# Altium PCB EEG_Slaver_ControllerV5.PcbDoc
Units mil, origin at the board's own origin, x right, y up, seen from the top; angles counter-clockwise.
Board outline 393.7 x 394 mil, 4 copper layers (Top Layer, GND, PWR, Bottom Layer), stack 30.634 mil thick; 41 components, 37 nets, 150 pads, 28 vias.
Unrouted connection lines stored in the file: 20.
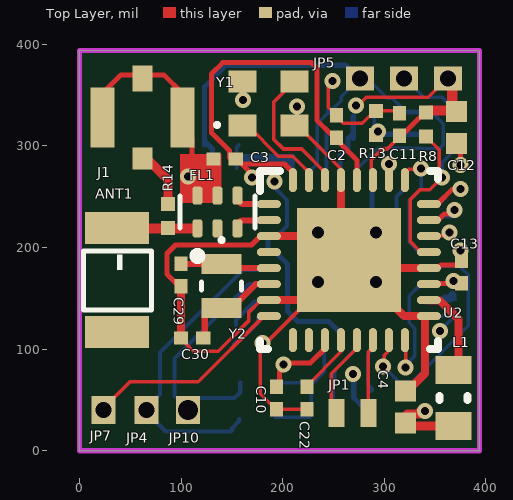
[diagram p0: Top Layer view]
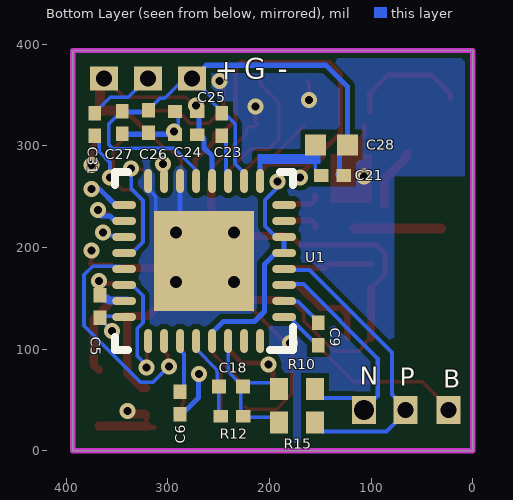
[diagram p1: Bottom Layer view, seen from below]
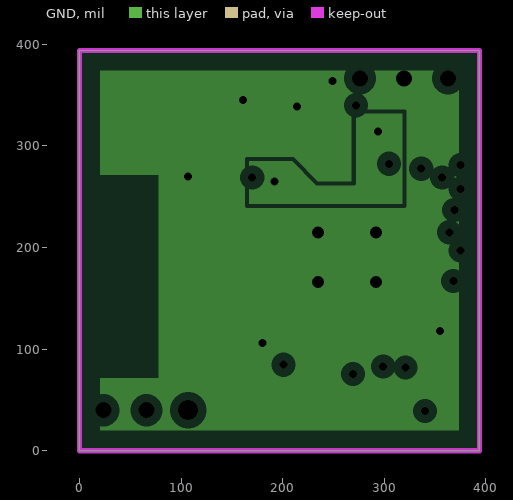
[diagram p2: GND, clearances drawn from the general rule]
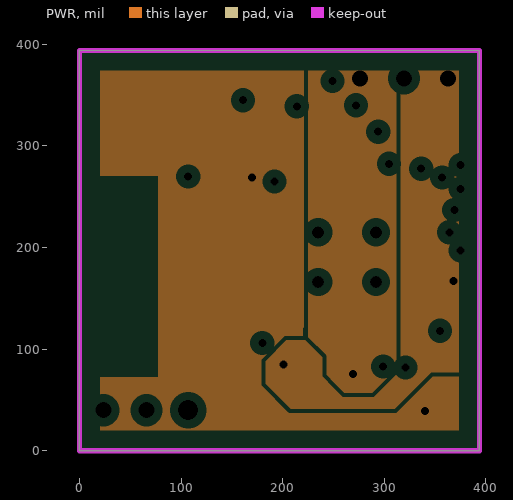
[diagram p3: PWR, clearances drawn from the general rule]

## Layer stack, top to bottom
Top Solder: solder mask 0.4, Solder Resist, Dk 3.5
Top Layer: signal copper 1.4
Dielectric 1: core 10, FR-4, Dk 4.2
GND: plane copper 1.417, net (Multiple Nets)
Dielectric 3: prepreg 5, Dk 4.2
PWR: plane copper 1.417, net (Multiple Nets)
Dielectric 2: core 10, Dk 4.2
Bottom Layer: signal copper 1.4
Bottom Solder: solder mask 0.4, Solder Resist, Dk 3.5

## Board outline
0,0 0,394 393.7,393.7 393.7,0

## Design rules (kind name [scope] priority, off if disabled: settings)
Clearance [All] p1: gap=5 ignorepadtopadclearanceinfootprint=FALSE except(3.5: Arc-Arc Arc-Track Track-Track)
DiffPairsRouting [All] p1: maxlimit=10 minlimit=10 mostfreqgap=10 toplayer_minwidth=3 toplayer_maxwidth=15 toplayer_prefwidth=15 bottomlayer_minwidth=3 bottomlayer_maxwidth=15 bottomlayer_prefwidth=15 maxuncoupledlength=500
MinimumSolderMaskSliver [All] p1: minsoldermaskwidth=8
PlaneClearance [All] p1: clearance=8
PlaneConnect [All] p1: planeconnectstyle=Direct reliefexpansion=20 reliefentries=4 reliefconductorwidth=10 reliefairgap=10
PolygonConnect [All] p1: connectstyle=Direct reliefconductorwidth=10 reliefentries=4 polygonreliefangle="90 Angle" airgapwidth=10
RoutingCorners [All] p1: cornerstyle=45-Degree minsetback=3.94 maxsetback=100
RoutingVias [All] p1: holewidth=7.87 width=15.75 viastyle="Through Hole" minholewidth=5.91 minwidth=11.81 maxholewidth=19.68 maxwidth=31.5
SolderMaskExpansion [All] p1: expansion=4
Width [All] p1: maxlimit=11 minlimit=3.5 preferedwidth=3.5 minimp=50.000000 maximp=50.000000 favimp=50.000000
25 further rules are at their usual default settings.

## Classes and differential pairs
differential pair IN1: +IN1_P -IN1_N
differential pair RF: +RF_P -RF_N

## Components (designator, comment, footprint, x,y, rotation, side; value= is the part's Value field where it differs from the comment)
ANT1 "2450AT18B100E" ANT_2450AT18B100E 37,168 r90 top
C2 "CAP" CAPC0201(0603)33_L 253,319 r90 top value=0.1uF
C3 "CAP" CAPC0201(0603)33_L 143,287 r180 top value=0.1uF
C4 "CAP" CAPC0402(1005)33_L 321,43 r90 top value=10uF
C5 "CAP" CAPC0201(0603)33_L 367,142 r90 bottom value=0.1uF
C6 "CAP" CAPC0201(0603)33_L 288,47 r90 bottom value=1uF
C9 "CAP" CAPC0201(0603)33_L 152,115.02 r90 bottom value=4.7nF
C10 "CAP" CAPC0201(0603)33_L 194,52 r270 top value=0.1uF
C11 "CAP" CAPC0201(0603)33_L 315,321 r90 top value=0.1uF
C12 "CAP" CAPC0402(1005)33_L 371,318 r270 top value=10uF
C13 "CAP" CAPC0201(0603)33_L 376,176 r90 top value=0.1uF
C18 "CAP" CAPC0201(0603)33_L 237,34 r180 bottom value=1.5nF
C21 "CAP" CAPC0201(0603)33_L 138,271 r0 bottom value=0.1uF
C22 "CAP" CAPC0201(0603)33_L 224,52 r270 top value=1uF
C23 "CAP" CAPC0201(0603)33_L 247,321 r270 bottom value=1uF
C24 "CAP" CAPC0201(0603)33_L 282,311 r180 bottom value=1uF
C25 "CAP" CAPC0201(0603)33_L 282,334 r180 bottom value=0.1uF
C26 "CAP" CAPC0201(0603)33_L 319,324 r90 bottom value=1uF
C27 "CAP" CAPC0201(0603)33_L 345,323 r90 bottom value=0.1uF
C28 "CAP" CAPC0402(1005)33_L 139,301 r0 bottom value=10uF
C29 "CAP" CAPC0201(0603)33_L 100,173 r270 top value=12pF
C30 "CAP" CAPC0201(0603)33_L 111,111 r180 top value=12pF
C31 "CAP" CAPC0201(0603)33_L 372,321 r90 bottom value=0.1uF
FL1 "2450BM14G0011T" BALUN_2450BM14G0011T 135.83,235 r90 top
J1 "CONREVSMA001-SMD-G" KH-IPEX3-2020 62,328 r90 top
JP1 "CON2" connect2 253,37 r0 top
JP4 "CON1" CON1_0.4#1 163,21.41 r90 top
JP5 "CON3" con3_0.5 319.49,366.52 r0 top
JP7 "CON1" CON1_0.4#2 53.55,77.41 r90 top
JP10 "CON1" CON1_0.4#3 107,36 r180 top
L1 "" RESC0603(1608)_L 368,52 r270 top value=10uH
R8 "RES" RESC0201(0603)_L 341,321 r90 top value=100k
R10 "RES" RESC0402(1005)_L 173,61 r180 bottom value=10M
R12 "RES" RESC0201(0603)_L 238,63 r180 bottom value=1M
R13 "RES" RESC0201(0603)_L 292,322.44 r270 top value=0
R14 "RES" RESC0201(0603)_L 87,231 r90 top value=0
R15 "RES" RESC0402(1005)_L 173,28 r180 bottom value=10M
U1 "ADS1291RIRSMT" ADS1291IRSMT 264.38,186.74 r0 bottom
U2 "CC2640R2FRSMR" CC2640R2F_RSM_32 265.24,187.62 r0 top value=Value
Y1 "7E024000M01" XTAL_ECS-240-6-37B-7KM-TR 186,342 r0 top
Y2 "ECS-.327-7-16-C-TR" XTAL_ECS-.327-7-16-C-TR 140,162 r270 top

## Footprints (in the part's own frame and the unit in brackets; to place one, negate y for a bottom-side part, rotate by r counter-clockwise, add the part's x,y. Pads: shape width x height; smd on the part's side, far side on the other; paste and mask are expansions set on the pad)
ADS1291IRSMT [mm] "QFN, 32-Leads, Body 4.00x4.00mm, Pitch 0.40mm, Thermal Pad 2.70x2.70mm, IPC Medium Density"
  oval 0.6x0.2 smd mask+0.05: 1(-2,1.4) 2(-2,1) 3(-2,0.6) 4(-2,0.2) 5(-2,-0.2) 6(-2,-0.6) 7(-2,-1) 8(-2,-1.4) 17(2,-1.4) 18(2,-1) 19(2,-0.6) 20(2,-0.2) 21(2,0.2) 22(2,0.6) 23(2,1) 24(2,1.4)
  oval 0.2x0.6 smd mask+0.05: 9(-1.4,-2) 10(-1,-2) 11(-0.6,-2) 12(-0.2,-2) 13(0.2,-2) 14(0.6,-2) 15(1,-2) 16(1.4,-2) 25(1.4,2) 26(1,2) 27(0.6,2) 28(0.2,2) 29(-0.2,2) 30(-0.6,2) 31(-1,2) 32(-1.4,2)
  rect 2.5x2.5 smd paste-0.5 mask+0.05: 33(0,0)
  silkscreen extent -2.22,-2.22 2.22,2.23, body extent -2.08,-2.07 2.07,2.08, height 1
ANT_2450AT18B100E [mm]
  rect 0.8x1.6 smd: 1(1.3,0) 2(-1.3,0)
  silkscreen extent -0.75,-0.86 0.73,0.84
BALUN_2450BM14G0011T [mm]
  rrect50% 0.45x0.25 smd: 1(-0.41,0.5) 2(-0.41,0) 3(-0.41,-0.5) 4(0.41,-0.5) 5(0.41,0) 6(0.41,0.5)
  silkscreen extent -1.2,-0.94 0.4,0.94
CAPC0201(0603)33_L [mm] "Chip Capacitor, Body 0.6x0.3mm, Height 0.33mm, IPC High Density"
  rect 0.36x0.32 smd mask+0.051: 1(-0.28,0) 2(0.28,0)
  body extent -0.32,-0.17 0.32,0.17, height 0.33
CAPC0402(1005)33_L [mm]
  rect 0.52x0.52 smd: 1(-0.4,0) 2(0.4,0)
  body extent -0.55,-0.3 0.55,0.3, height 0.33
CC2640R2F_RSM_32 [mm]
  oval 0.6x0.2 smd paste+0 mask+0.051: 1(-2,1.4) 2(-2,1) 3(-2,0.6) 4(-2,0.2) 5(-2,-0.2) 6(-2,-0.6) 7(-2,-1) 8(-2,-1.4) 17(2,-1.4) 18(2,-1) 19(2,-0.6) 20(2,-0.2) 21(2,0.2) 22(2,0.6) 23(2,1) 24(2,1.4)
  oval 0.2x0.6 smd paste+0 mask+0.051: 9(-1.4,-2) 10(-1,-2) 11(-0.6,-2) 12(-0.2,-2) 13(0.2,-2) 14(0.6,-2) 15(1,-2) 16(1.4,-2) 25(1.4,2) 26(1,2) 27(0.6,2) 28(0.2,2) 29(-0.2,2) 30(-0.6,2) 31(-1,2) 32(-1.4,2)
  rect 2.6x2.6 smd paste-1.387 mask+0.051: 33(0,0)
  silkscreen extent -2.23,-2.23 2.23,2.23, body extent -1.63,-1.63 1.63,1.63, height 0.25
CON1_0.4#1 [mm]
  rect 0.7x0.6 hole 0.4: 1(0.47,2.464)
CON1_0.4#2 [mm]
  rect 0.7x0.6 hole 0.4: 1(-0.952,0.76)
CON1_0.4#3 [mm]
  rect 0.6x0.7 hole 0.5: 1(0,-0.1)
con3_0.5 [mm]
  rect 0.7x0.6 hole 0.4: 1(-1.1,0) 2(0,0) 3(1.1,0)
connect2 [mm]
  rect 0.4x0.7 smd: 1(0.8,0) 2(0,0)
KH-IPEX3-2020 [mm]
  rect 0.55x0.5 smd: 1(-1.025,0)
  rect 1.5x0.6 smd: 2(0,-1) 4(0,1)
  rect 0.65x0.5 smd: 3(0.98,0)
RESC0201(0603)_L [mm] "Chip Resistor, Body 0.6x0.3mm, IPC High Density"
  rect 0.35x0.35 smd mask+0.051: 1(-0.3,0) 2(0.3,0)
  body extent -0.31,-0.16 0.31,0.16, height 0.3
RESC0402(1005)_L [mm]
  rect 0.45x0.55 smd: 1(-0.45,0) 2(0.45,0)
  body extent -0.52,-0.27 0.53,0.28, height 0.4
RESC0603(1608)_L [mm] "Chip Resistor, Body 1.6x0.8mm, IPC High Density"
  rect 0.7x0.9 smd: 1(-0.7,0) 2(0.7,0)
  silkscreen extent -0.05,-0.35 0.05,0.35, body extent -0.85,-0.47 0.85,0.47, height 0.6
XTAL_ECS-240-6-37B-7KM-TR [mm]
  rect 0.7x0.55 smd: 1(-0.65,-0.55) 2(0.65,-0.55) 3(0.65,0.55) 4(-0.65,0.55)
  silkscreen extent -1.34,-0.59 -1.24,-0.49
XTAL_ECS-.327-7-16-C-TR [mm]
  rect 0.5x1 smd: 1(-0.55,0) 2(0.55,0)
  silkscreen extent -1.2,-0.5 0.1,0.5

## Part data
ANT1: "2.4GHz Chip RF Antenna 2.4GHz ~ 2.5GHz 0.5dBi Solder Surface Mount", Package=None
C2 C3 C10 C11 C13 C31: "CAP, CERM, 0.1 uF, 25 V, +/- 10%, X7R, 0402"
C4: "CAP, CERM, 10 uF, 25 V, +/- 20%, X5R"
C5 C6 C9 C18 C21 C22 C23 C24 C25 C26 C27 C28 C29 C30: "Capacitor General"
C12: "CAP, CERM, 10 uF, 25 V, +/- 20%, X5R, 0603"
FL1: "RF Balun 2.4GHz ~ 2.5GHz 50 / -Ohm 0603 _1608 Metric_", Package="0603 Johanson"
J1: library part SMA-KH-IPEX3-2020, "Connector, SMA, Vertical, Gold, SMT", Manufacturer="Linx Technologies Inc.", Supplier Part Number 1=CONREVSMA001-SMD-G-ND
L1: library part Inductor, "Inductor, Multilayer, Ferrite, 10 uH, 0.11 A, 0.52 ohm, SMD"
R8 R10 R12 R14 R15: "RES, 100 k, 1%, 0.1 W, 0402", Tolerance=0.1%
R13: "Resistor General", Tolerance=0.1%
U1: library part ADS1291/1292
U2: "Imported", Manufacturer="Texas Instruments"
Y1: library part ECS-240-6-37B-7KM-TR, "24MHz 12pF ±10ppm,SMD-1612_4P,80Ω", Package="SMD-4 ECS International"
Y2: "32.768kHz ?±10ppm Crystal 7pF 90 kOhms 2-SMD, No Lead", Package="SMD-2 ECS International"

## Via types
v1: diameter 15.75, hole 7.87, Top Layer to Bottom Layer, tented both sides, 24 vias
v2: diameter 23.62, hole 11.81, Top Layer to Bottom Layer, tented both sides, 4 vias

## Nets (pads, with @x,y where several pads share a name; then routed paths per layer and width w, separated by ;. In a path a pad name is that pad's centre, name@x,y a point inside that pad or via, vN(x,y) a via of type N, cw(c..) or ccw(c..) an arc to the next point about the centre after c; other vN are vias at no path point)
2V5_A: C5.2 C10.1 C11.1 C12.1 C13.1 C24.2 C25.2 JP5.3 R8.2 U1.12 U1.23 U2.11 U2.19 U2.27 | length 479.4
  Top Layer w3.5: v1(272.24,339.99) 273.59,339.99 274,339.58 282.38,347.96 343.25,347.96 JP5.3@357,361.71 ; U2.27@287,265 287,286 297.99,296.99 302.8,296.99 313,307.19 C11.1@313,309 ; C11.1@314,308 316,310 C11.1@316,311
  Top Layer w4: JP5.3@357,361.71 JP5.3@361.81,366.52
  Top Layer w5: C10.1 196.73,65.75 196.73,77.61 200.91,81.79 v1(200.91,84.7) ; v1@201,85 202.48,86.48 227.52,86.48 241.61,100.58 U2.11 U2.11@241.61,117.18 ; C11.1@317,310 324.41,317.41 330.55,323.58 ; 330.58,323.58 339.81,332.81 R8.2 ; U2.19 344.53,164.55 U2.19@346.55,164.55 ; U2.19@345.45,163.45 U2.19@346.55,164.55 ; C13.1@371,168 366.09,168 362.64,164.55 U2.19@346.55,164.55
  Top Layer w10: R8.2@344,335 369.75,335 C12.1 ; JP5.3@365,367 366.9,365.1 C12.1@366.9,337.85
  Bottom Layer w3.5: U1.23@340.3,148 341.3,149 U1.23@343.12,149 ; C5.2@367,149 C5.2@369.76,149
  Bottom Layer w5: U1.12 256.5,290 264.39,297.89 264.39,307.2 267.19,310 C24.2@269,310 ; C24.2@269.48,307.5 C25.2@269.48,329.2
  Bottom Layer w8: U1.23@340.3,148 357.91,148 359.91,150 364.76,150 367,152.24 C5.2
  other v1: 368,167
-2V5_A: C6.1 C21.1 C23.1 C26.2 C27.2 C28.1 JP5.1 U1.10 U1.13 | length 682
  Bottom Layer w3.5: U1.10 225.01,273.35 234,282.35 234,302.04 233.95,302.09 233.95,321.86 237.9,325.81 237.9,325.9 244,332 C23.1@246,332 ; C23.1@244,335.02 248.02,335.02 257.61,344.61 257.61,348.29 268,358.68 JP5.1@268,363 ; C23.1@244.72,333.28 245.45,334 C23.1@246,334 ; U1.13@272,276 293.62,297.62 335.42,297.62 335.9,297.14 351.91,297.14 352,297.05 ; U1.13 272.25,273.35 U1.13@273.45,274.55 ; JP5.1 283.43,366.52 302.98,346.98 307.84,346.98 317,337.81 C26.2@317,333 ; C26.2@319,333 C27.2@344.98,333 ; C27.2@345,333.02 345,332.24 346.24,331 349,331 358.05,321.95 358.05,301.09 353.96,297 352,297
  Bottom Layer w5: C28.1@124,304 C28.1@125.13,302.87 ; C21.1@132.98,272 130.99,273.99 130.99,297.01 C28.1@125.13,302.87 ; v1@272,72 270,70 270,52.03 282.03,40 284.76,40 287,37.76 C6.1@287,36.98 ; JP5.1@272,363 272,369.72 262.34,379.37 144.37,379.37 123.25,358.25 C28.1 C28.1@125.13,302.87 ; C26.2@319,333 319.52,333.52 344.5,333.52 C27.2@345,333.02
  other v1: 269.25,75.54
AFE_CLK: U1.17 U2.24 | length 77.1
  Top Layer w5: U2.24 352.48,242.74 367.49,257.75 v1(375.09,257.75)
  Bottom Layer w5: U1.17@341.55,241.74 U1.17@342.39,242.58 ; U1.17 351.6,241.86 367.49,257.75 v1(375.09,257.75)
AFE_CS#: U1.18 U2.23 | length 51.4
  Top Layer w5: U2.23 344.53,227.54 353.54,227.54 359,233 v1@368,233
  Bottom Layer w5: U1.18 343.67,226.66 352.66,226.66 357,231 v1@366,231
  other v1: 369,237
AFE_DRDY#: U1.22 U2.16 | length 120.6
  Top Layer w3.5: U2.16@320,101.68 321,100.68 v1(321,82)
  Bottom Layer w3.5: v1@320,82 v1(321,82) 321,84 330.18,93.18 330.18,120.3 324.56,125.93 324.56,152.43 335.24,163.12 U1.22
AFE_MISO: U1.21 U2.15 | length 238.5
  Top Layer w3.5: v1@297,85 300,88 300,94 304.36,98.36 304.36,108.63 U2.15 ; U2.15@305,110 U2.15@305.54,109.46
  Bottom Layer w3.5: v1@297,85 v1(299,83) 314.62,67.38 327.06,67.38 382.62,122.94 382.62,173.06 374.06,181.62 346.59,181.62 346.59,180.89 344.57,178.87 U1.21
AFE_MOSI: U1.19 U2.22 | length 37.9
  Top Layer w4: U2.22 344.72,211.98 357.81,211.98 359.82,214 v1@365,214
  Bottom Layer w4: U1.19@340.55,211.24 344,211.24 344.76,212 356,212
  other v1: 364,215
AFE_RESET#: U1.15 U2.26 | length 16.7
  Top Layer w4: U2.26 304.09,266.87 305,267.78 304.71,268.07 v1(304.71,282.37)
AFE_SCK: U1.20 U2.25 | length 131.2
  Top Layer w3.5: U2.25@320,269 U2.25@320,274.19 ; U2.25 320.35,273.05 324.3,277 330.38,277 332.38,279 v1@337,279
  Bottom Layer w3.5: v1(336.31,277.65) 336.31,258.03 324.56,246.28 324.56,205.3 335.24,194.61 U1.20
BAT_SENSE: JP7.1 U2.8 | length 200.4
  Top Layer w3.5: JP7.1@24,45 26.73,45 49.73,68 117,68 180.65,131.65 179.81,132.5 U2.8
DCDC_SW: L1.1 U2.18 | length 88.8
  Top Layer w8: U2.18@344,148 354.65,148 373,129.65 373,84.56 L1.1
GND: C2.2 C3.2 C4.2 C5.1 C10.2 C11.2 C12.2 C13.2 C22.2 C29.2 C30.2 C31.2 FL1.5 FL1.6 J1.2 J1.3 J1.4 JP5.2 R13.1 U1.14 U1.16 U1.24 U1.33 U2.3 U2.7 U2.17 U2.20 U2.29 U2.33 Y1.2 Y1.4 | length 1636.5
  Top Layer w3.5: C30.2@101,111 105.31,106.69 105.31,104.78 112.14,97.95 136.68,97.95 166.43,127.71 166.43,136.06 178.62,148.25 U2.7 ; v1(161,345) 161,361.06 163,363.06 Y1.4@162.41,363.65 ; v1@178,104 178,100 178,56.09 184.9,49.19 184.9,49.1 193.02,40.98 C10.2 221.98,40.98 C22.2@224,43 ; Y1.2@213.59,320.35 212,321.94 214,323.94 v1(214,339) ; Y1.2@215,319 220.89,319 223,316.89 223,312 257.36,277.64 U2.29 ; v1(249,364) 244.95,359.95 244.95,338.07 C2.2 253,329.24 257.55,324.69 257.55,324.45 259.75,322.25 278.29,322.25 289.04,333 R13.1@292,333 ; U2.33@257,204 U2.33@257.36,204.36 ; U2.33@290.75,179.75 U2.33@307,179.75 ; R13.1@292,334.81 315.81,334.81 C11.2@316,335 ; JP5.2@313,362 JP5.2@316,365 ; v1@353,116 v1@354,116 ; v1@356,118 v1@356,119.46 ; C13.2@371.45,191.57 C13.2
  Top Layer w4: 135,264 137,266 ; 135,268 136,267 ; v1@180,100 v1@184.25,104.25 ; v1@184.25,106.63 225.87,148.25 239.31,161.69 U2.33
  Top Layer w5: J1.4@22,346 22,351.09 40.91,370 83.09,370 101.37,351.72 J1.2@101.37,334 ; C29.2@99.98,160.02 86.2,173.8 86.2,194.22 94.44,202.46 169.41,202.46 178.2,211.24 U2.3 ; J1.2@107,320 107,310.65 110.68,306.97 110.68,287 C3.2 ; FL1.6@115,255 115,254.71 118.56,251.14 FL1.5 133.9,253.07 133.9,285.1 C3.2@133,286 ; U2.33@230.24,211.24 U2.33@232,213 ; U2.33@307,183 308.63,181.37 U2.33@310.25,179.75 ; U2.33@310,150 310,142.86 U2.33@313.43,139.43 ; U2.20 344.53,180.3 353.3,180.3 355.94,182.94 374.94,182.94 C13.2@376,184 ; C12.2 375,298.25 375,283 v1@374,282
  Top Layer w8: C30.2 C29.2@99.98,160.02 ; U2.7 U2.33@225.87,148.25 ; U2.3 U2.33@230.24,211.24 ; U2.33@257.36,204.36 U2.29 ; U2.33@310.25,179.75 U2.20 ; U2.33@313,139 319.5,132.5 U2.17 ; C4.2@321,61.75 325.75,61.75 340,76 340,128
  Bottom Layer w3.5: U1.14@288,260 U1.14 ; U1.33@294,228 305.64,228 312.09,234.45 312.09,250.2 319.5,257.61 U1.16 ; JP5.2@327,359.99 339.03,347.96 356.85,347.96 372,332.81 C31.2 ; U1.24@340.55,132.5 C5.1@367,132.5 ; v1(355,118) 355,118.19 367,130.19 C5.1
  Bottom Layer w5: U1.33 288,210.36 288,260 U1.14@287,261
  other v1: 180,106 375,197 107,270 375,281
  other v2: 235,166 292,166 235,215 292,215
GND_A: C24.1 C25.1 C26.1 C27.1 R13.2 U1.5 U1.6 U1.29 | length 304
  Bottom Layer w3.5: C25.1@288,336 C25.1@289.01,334.99 ; C24.1@290.02,311 290.02,311.49 C25.1@290.02,333.98
  Bottom Layer w4: U1.6 193.51,210.36 204.45,221.3 204.45,246.55 192,259 v1(192,265)
  Bottom Layer w5: U1.5 185.64,209.64 U1.6@186,210 ; U1.5@190,194 194.55,194 204.95,183.6 204.95,137.14 214.78,127.31 245.49,127.31 256.5,116.3 U1.29 ; C24.1@290,309 292.49,311.49 318.51,311.49 C26.1@319,311.98 ; C26.1@318,311.98 C26.1@318.98,311.98 ; C27.1@345,310.98 344.5,311.48 319.52,311.48 C26.1@319,312
  other v1: 294,314
IN1_N: JP10.1 R10.2 U1.3 | length 246.9
  Bottom Layer w4: JP10.1 107,41.89 97.19,51.7 95.84,51.7 93.5,54.04 93.5,90.83 166.66,163.99 174.15,163.99 174.28,163.86 184.9,163.86 U1.3 ; JP10.1@108,42 108,42.89 116.81,51.7 152.7,51.7 158.28,57.28 R10.2@158.28,67
IN1_P: JP4.1 R15.2 U1.4 | length 310.8
  Bottom Layer w4: R15.2@157.28,31 157.28,29.03 150.43,22.17 150.43,20.43 149,19 84.95,19 66,37.95 JP4.1 66,41.89 73.84,49.73 73.84,49.84 79.5,55.5 79.5,96.63 160.86,177.99 174.15,177.99 174.28,178.12 184.9,178.12 U1.4
JTAG_RST: C31.1 R8.1 U2.21 | length 197.2
  Top Layer w3.5: R8.1 354.01,296.18 v1@354.01,270.99 ; U2.21 336.1,195.5 325.42,206.18 325.42,247.17 335.16,256.91 344.91,256.91 v1(357,269)
  Bottom Layer w3.5: v1@359,268 357,270 357,283.68 367.45,294.13 367.45,305.43 C31.1
JTAG_TCKC: JP1.1 U2.14 | length 70
  Top Layer w3.5: U2.14@285.95,98.95 284.38,97.38 284.38,47.62 285.95,46.05 285.95,44.05 288.86,41.14 288.86,33.86 JP1.1@288,33 ; U2.14 288.86,109.86 U2.14@289,110
JTAG_TMSC: JP1.2 U2.13 | length 87.3
  Top Layer w3.5: JP1.2@251,35 JP1.2 248,42 248,75.9 273.11,101.01 U2.13 U2.13@273,109
NetANT1_1: ANT1.1 FL1.1 R14.1 | length 85.2
  Top Layer w6: ANT1.1@31,219 ANT1.1@31.14,218.86
  Top Layer w10: ANT1.1@31.14,218.86 FL1.1
NetC6_2: C6.2 U1.27 | length 48.3
  Bottom Layer w4: C6.2@287,59.02 288,60.02 288,61 284.13,64.87 284.13,95.13 288,99 U1.27@288,103.7
NetC9_1: C9.1 U1.1 | length 47.1
  Bottom Layer w4: C9.1@152,105 156.09,109.09 158.32,109.09 176,126.76 176,131 176.62,131.62 U1.1
NetC9_2: C9.2 U1.2 | length 44.2
  Bottom Layer w4: C9.2@154,124 154,128.83 172.17,147 177.39,147 177.76,147.37 U1.2
NetC18_1: C18.1 R12.1 U1.28 | length 81.2
  Bottom Layer w3.5: C18.1@250.02,34 250.02,67.02 251,68 251.81,79.81 272.25,100.25 272.25,105.25 U1.28@273,106
NetC22_1: C22.1 U2.12 | length 60.4
  Top Layer w3.5: C22.1@224.59,59.41 224.59,64.59 257.36,97.36 257.36,105.36 U2.12@258,106
NetJ1_1: J1.1 R14.2 | length 58.3
  Top Layer w9: J1.1@65,292 65,289 87,267 R14.2
RF_N: FL1.3 U2.2 | length 35.7
  Top Layer w6: FL1.3@155,220 155,222.28 159.46,226.74 186.24,226.74 U2.2
RF_P: FL1.4 U2.1 | length 36.8
  Top Layer w6: FL1.4@155,251 155,247.72 159.98,242.74 U2.1
RLDOUT: C18.2 R10.1 R12.2 R15.1 U1.30 | length 151.4
  Bottom Layer w3.5: R10.1@191,67 R12.2@226,67 ; R15.1@193,33 C18.2@226.98,33 ; R12.2@226,66 R12.2@228.19,66 ; C18.2@227,34 228.19,35.19 228.19,65 R12.2@228.19,66 ; U1.30 240.76,77.76 233.33,70.33 233.33,70.14 229.19,66 R12.2@228.19,66
U0_RX: U2.9
U0_TX: U2.10
VCAP1: C23.2 U1.11 | length 50.4
  Bottom Layer w4: U1.11 243,267.72 C23.2@243,315
VDDR: C2.1 C3.1 C4.1 L1.2 U2.28 U2.32 | length 502.8
  Top Layer w5: C3.1@149.44,287 149,287 147.5,288.5 147.5,295.47 130,312.97 130,371 140.98,381.98 228.48,381.98 233.63,376.83 233.63,325.41 248.03,311 249.24,311 250,311.76 C2.1@250,310 ; C3.1@153,287 C3.1 154.81,287 C3.1@157.81,284 ; v1(170,269) 170,271.81 C3.1@157.81,284 ; U2.32 210.12,273.88 201.75,282.25 159.56,282.25 C3.1@157.81,284 ; C2.1@250,307 252,307 273.11,285.89 U2.28 ; C2.1@254,307 C2.1@254,312 ; C4.1@313.75,23 C4.1@319,23 ; C4.1@320,33 C4.1@322,35 ; C4.1@321,31 C4.1@321.5,31.5
  Top Layer w9: C4.1@320.44,24.44 L1.2 ; C4.1@322,35 322.99,35.99 335.01,35.99 335.74,36.71 335.74,37.29 335,38.03 335.97,39 v1(340,39)
VREF_P: C21.2 C28.2 U1.9 | length 45.4
  Bottom Layer w3.5: 155.02,278 155.02,299.02 C28.2@157,301
  Bottom Layer w5: 209,287 209.26,286.74 U1.9
X24M_N: U2.30 Y1.3 | length 137.6
  Top Layer w3.5: Y1.3@209,365 209,361 191.06,343.06 191.06,306.72 200.78,297 218.85,297 241.61,274.24 U2.30
X24M_P: U2.31 Y1.1 | length 86.9
  Top Layer w3.5: Y1.1@166,320 166,319.71 195.71,290 210.1,290 225.87,274.24 U2.31
X32K_Q1: C29.1 U2.5 Y2.1 | length 83.8
  Top Layer w6: C29.1@99.65,183.65 Y2.1 ; Y2.1@144,182 146.25,179.75 U2.5
X32K_Q2: C30.1 U2.6 Y2.2 | length 118.4
  Top Layer w3.5: C30.1 C30.1@123.31,112.29 ; C30.1@125,113.98 Y2.2@125,135.19 ; U2.6@177,163.07 182.07,163.07 U2.6@183,164
  Top Layer w6: C30.1@123,111 123.31,111.31 123.31,112.29 123.31,133.5 125,135.19 130.16,140.35 Y2.2 149.84,140.35 173.5,164 U2.6@177,164
pads on no net: ANT1.2 FL1.2 U1.7 U1.8 U1.25 U1.26 U1.31 U1.32 U2.4

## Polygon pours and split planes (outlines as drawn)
no net on Top Layer "Top Layer-No Net" (solid, pour order 8): 17.49,405
GND on Bottom Layer (solid, remove dead copper, pour order 22): -1,2 0,1 393,1 393,396 392,395 -3,395
no net on Bottom Layer (solid, pour order 12): 149,295
no net on Bottom Layer "Bottom Layer-No Net" (solid, pour order 10): -14.51,-25
GND_A on GND (split plane): 277,331.96 317.96,331.96 317.96,243.04 167.04,243.04 167.04,284.96 209.16,284.96 232.56,261.56 233.22,261.12 234,260.96 270,260.96 270.78,261.12 271.44,261.56 271.88,262.22 272.04,263 272.04,327.16 276.87,331.99
GND on GND (split plane): 373.6,373.62 373.6,20.1 20.1,20.1 20.1,72 77.49,72 77.49,271 20.1,271 20.1,373.89
-2V5_A on PWR (split plane): 311.96,373.67 311.96,138 311.96,134 311.96,80.84 288.16,57.04 260.84,57.04 252.19,65.69 243.04,74.84 243.04,93 242.88,93.78 242.44,94.44 225.04,111.84 225.04,373.73
2V5_A on PWR (split plane): 373.6,373.62 373.6,77.04 347,77.04 346.22,76.88 345.56,76.44 310.16,41.04 207.84,41.04 183.04,65.84 183.04,88.16 203.84,108.96 222,108.96 222.13,108.99 238.96,92.16 238.96,74 239.12,73.22 239.56,72.56 249.31,62.81 258.56,53.56 259.22,53.12 260,52.96 289,52.96 289.78,53.12 290.44,53.56 315.44,78.56 315.88,79.22 316.04,80 316.04,138 316.04,373.66
VDDR on PWR (split plane): 220.96,373.74 220.96,121.71 220.56,121.44 220.12,120.78 219.96,120 219.96,113.04 203,113.04 202.22,112.88 201.56,112.44 179.56,90.44 179.12,89.78 178.96,89 178.96,65 179.12,64.22 179.56,63.56 205.56,37.56 205.95,37.29 206.22,37.12 207,36.96 311,36.96 311.78,37.12 312.44,37.56 347.84,72.96 373.6,72.96 373.6,20.1 20.1,20.1 20.1,73 76.99,73 76.99,270 20.1,270 20.1,373.89

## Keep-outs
Keep-Out Layer:
  the board outline again, w5

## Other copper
Top Layer:
  rectangle net GND: 99,244 140,292
  pour cut-out: 0,72 77.49,72 77.49,270 0,270
Bottom Layer:
  rectangle net VREF_P: 150,282 212,292
  pour cut-out: 0,72 77.49,72 77.49,270 0,270
GND (plane layer: these items are gaps in the copper):
  pour cut-out: 0,72 77.49,72 77.49,271 0,271 0,262.96
  lines w4: 276,334 270,328 270,263 234,263 210,287 165,287 165,241 320,241 320,334 277,334
PWR (plane layer: these items are gaps in the copper):
  pour cut-out: -0.5,73 76.99,73 76.99,270 4.5,270 -0.5,270
  lines w4: 222,120 222,111 203,111 181,89 181,65 207,39 311,39 347,75 394,75 ; 223,394 223,111 241,93 241,74 250.75,64.25 260,55 289,55 314,80 314,138 ; 314,134 314,394 ; 393,133 394,134
  lines w5: 317,393 318,394 ; 393,42 393,51

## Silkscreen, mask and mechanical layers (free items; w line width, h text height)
Bottom Overlay:
  text "-" at 192,366 h20
  text "G" at 225,366 h20
  text "+" at 254,365 h20
  text "N" at 111,65 h18
  text "P" at 72,64 h18
  text "B" at 29,62 h18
